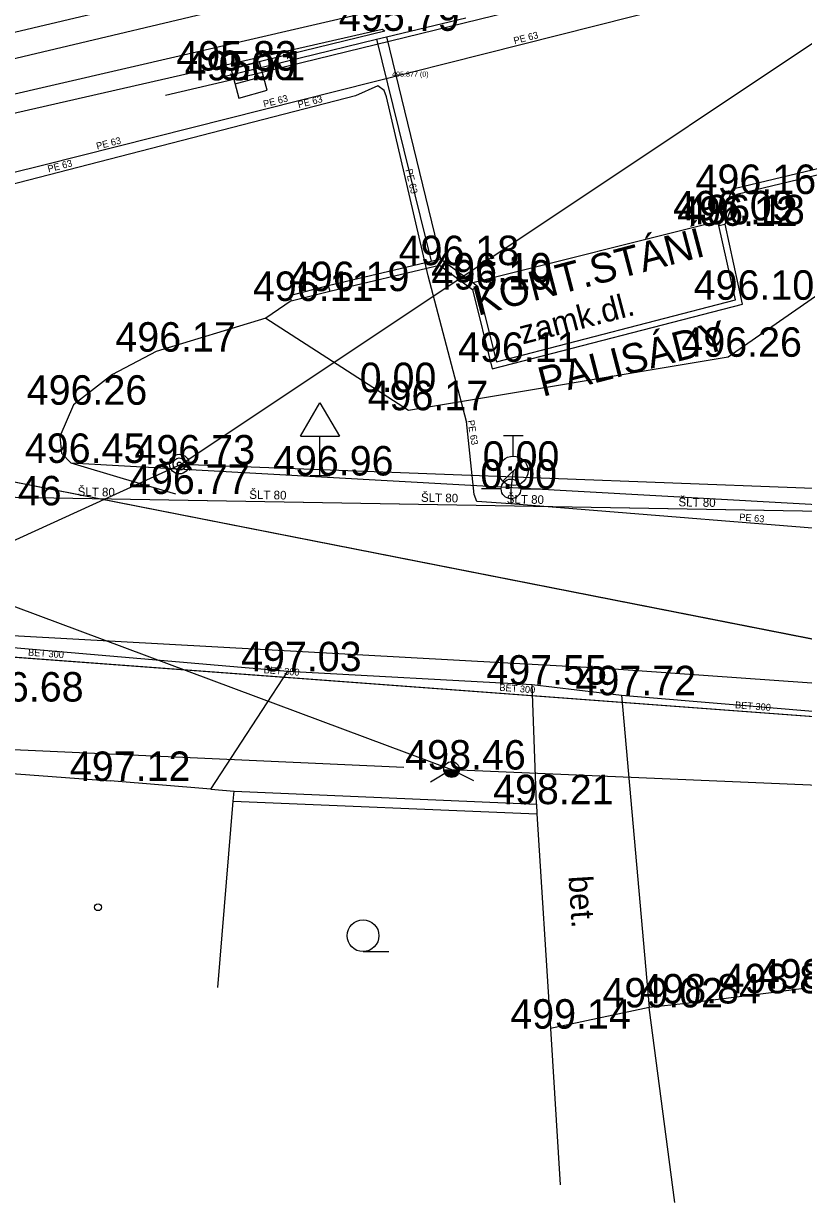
# Model space of a CAD drawing. Extents: x -669642 to -669119, y -1131006 to -1130466.
# Drawn here: x -669378.41 to -669358.57, y -1130646.29 to -1130616.3 of the extents above; entities that cross this region are included whole.
import ezdxf

# ---------------------------------------------------------------- set-up
doc = ezdxf.new("R2010")
doc.units = 0
for name, color, linetype in [('G_Bod_tecka', 7, 'Continuous'), ('G_Bod_vyska', 7, 'Continuous'), ('G_Breh_Teren', 7, 'Continuous'), ('G_Budovy-znacky', 7, 'Continuous'), ('G_Budovy_Objekty', 7, 'Continuous'), ('G_Budovy_vstupy', 7, 'Continuous'), ('G_Cesty_Schody', 7, 'Continuous'), ('G_Objekty_dopravni', 7, 'Continuous'), ('G_Plochy_zpevnene', 7, 'Continuous'), ('G_Ploty', 7, 'Continuous'), ('G_Ploty_vstupy', 7, 'Continuous'), ('G_Popisy_povrchu', 7, 'Continuous'), ('G_Poznamky_odkaz', 7, 'Continuous'), ('G_Site-kanalizace', 7, 'Continuous'), ('G_Site-Sloupy', 7, 'Continuous'), ('G_Site-vodovod', 7, 'Continuous'), ('G_Z_ELsilove_nadz_kotovane', 7, 'Continuous'), ('G_Z_ELsilove_podz_kotovane', 7, 'Continuous'), ('G_Z_KANAL_podz_kotovane', 7, 'Continuous'), ('G_Z_KANAL_podz_priblizne', 7, 'Continuous'), ('G_Z_PLYNY_podz_geodeticky', 7, 'Continuous'), ('G_Z_SPOJE_nadz_kotovane', 7, 'Continuous'), ('G_Z_VODA_podz_kotovane', 7, 'Continuous'), ('G_Zabradli_Svodidla', 7, 'Continuous'), ('G_Zelen-Znacky', 7, 'Continuous'), ('Vrstva 13', 7, 'Continuous'), ('Vrstva 17', 7, 'Continuous'), ('Vrstva 2', 7, 'Continuous'), ('Vrstva 21', 7, 'Continuous'), ('Vrstva 22', 7, 'Continuous'), ('Vrstva 25', 7, 'Continuous'), ('Vrstva 3', 7, 'Continuous'), ('Vrstva 4', 7, 'Continuous'), ('Vrstva 62', 7, 'Continuous'), ('Vrstva 8', 7, 'Continuous')]:
    doc.layers.add(name, color=color, linetype=linetype)

msp = doc.modelspace()

# ---------------------------------------------------------------- linework, layer by layer
at = {"layer": 'G_Bod_tecka'}
for p, q in [((-669369.22, -1130616.49), (-669369.22, -1130616.49)), ((-669373.36, -1130617.5), (-669373.36, -1130617.5)), ((-669373.21, -1130617.75), (-669373.21, -1130617.75)), ((-669372.67, -1130617.74), (-669372.67, -1130617.74)), ((-669360.26, -1130620.64), (-669360.26, -1130620.64)), ((-669360.74, -1130621.45), (-669360.74, -1130621.45)), ((-669360.68, -1130621.31), (-669360.68, -1130621.31)), ((-669360.56, -1130621.41), (-669360.56, -1130621.41)), ((-669367.83, -1130622.45), (-669367.83, -1130622.45)), ((-669366.99, -1130623.07), (-669366.99, -1130623.07)), ((-669366.98, -1130622.89), (-669366.98, -1130622.89)), ((-669371.6, -1130623.36), (-669371.6, -1130623.36)), ((-669370.62, -1130623.11), (-669370.62, -1130623.11)), ((-669360.3, -1130623.33), (-669360.3, -1130623.33)), ((-669375.04, -1130624.65), (-669375.04, -1130624.65)), ((-669360.48, -1130624.78), (-669360.48, -1130624.78)), ((-669366.38, -1130624.91), (-669366.38, -1130624.91)), ((-669369.08, -1130625.68), (-669369.08, -1130625.68)), ((-669377.14, -1130626), (-669377.14, -1130626)), ((-669368.62, -1130626.14), (-669368.62, -1130626.14)), ((-669377.21, -1130627.48), (-669377.21, -1130627.48)), ((-669374.41, -1130627.52), (-669374.41, -1130627.52)), ((-669370.87, -1130627.8), (-669370.87, -1130627.8)), ((-669365.95, -1130627.68), (-669365.95, -1130627.68)), ((-669366.01, -1130628.14), (-669366.01, -1130628.14)), ((-669374.55, -1130628.27), (-669374.55, -1130628.27)), ((-669371.69, -1130632.78), (-669371.69, -1130632.78)), ((-669365.47, -1130633.12), (-669365.47, -1130633.12)), ((-669363.2, -1130633.39), (-669363.2, -1130633.39)), ((-669367.52, -1130635.28), (-669367.52, -1130635.28)), ((-669376.21, -1130635.57), (-669376.21, -1130635.57)), ((-669365.36, -1130636.16), (-669365.36, -1130636.16)), ((-669359.46, -1130640.97), (-669359.46, -1130640.97)), ((-669362.49, -1130641.33), (-669362.49, -1130641.33)), ((-669361.55, -1130641.23), (-669361.55, -1130641.23)), ((-669365, -1130641.87), (-669365, -1130641.87))]:
    msp.add_line(p, q, dxfattribs=at)
at = {"layer": 'G_Breh_Teren'}
for p, q in [((-669348.63, -1130609.42), (-669399.78, -1130621.54)), ((-669348.48, -1130610.05), (-669399.67, -1130622.18)), ((-669373.65, -1130635.78), (-669371.69, -1130632.78))]:
    msp.add_line(p, q, dxfattribs=at)
for points in [[(-669372.25, -1130623.8), (-669368.62, -1130626.14), (-669360.48, -1130624.78), (-669351.48, -1130618.53)], [(-669377.21, -1130627.48), (-669354.27, -1130628.76), (-669343.54, -1130629.51), (-669334.11, -1130630.08), (-669322.15, -1130630.73)]]:
    msp.add_lwpolyline(points, dxfattribs=at)
at = {"layer": 'G_Budovy-znacky'}
msp.add_circle((-669376.519, -1130638.78), 0.0875, dxfattribs=at)
at = {"layer": 'G_Budovy_Objekty'}
for p, q in [((-669360.72, -1130621.44), (-669360.56, -1130621.41)), ((-669360.3, -1130623.33), (-669360.72, -1130621.44)), ((-669360.12, -1130623.44), (-669360.56, -1130621.41)), ((-669366.99, -1130623.07), (-669366.86, -1130622.98)), ((-669366.99, -1130623.07), (-669366.49, -1130625.09)), ((-669366.86, -1130622.98), (-669366.38, -1130624.91)), ((-669366.38, -1130624.91), (-669360.3, -1130623.33)), ((-669366.49, -1130625.09), (-669360.12, -1130623.44)), ((-669378.82, -1130635.37), (-669376.21, -1130635.57)), ((-669373.65, -1130635.78), (-669373.05, -1130635.83)), ((-669373.08, -1130636.08), (-669373.05, -1130635.83)), ((-669373.47, -1130640.82), (-669373.08, -1130636.08)), ((-669358.56, -1130640.85), (-669359.46, -1130640.97)), ((-669361.55, -1130641.23), (-669362.49, -1130641.33)), ((-669361.84, -1130646.29), (-669362.49, -1130641.33))]:
    msp.add_line(p, q, dxfattribs=at)
at = {"layer": 'G_Budovy_vstupy'}
for p, q in [((-669373.65, -1130635.78), (-669376.21, -1130635.57)), ((-669359.46, -1130640.97), (-669361.55, -1130641.23))]:
    msp.add_line(p, q, dxfattribs=at)
at = {"layer": 'G_Cesty_Schody'}
for p, q in [((-669369.43, -1130616.7), (-669369.18, -1130616.64)), ((-669369.18, -1130616.64), (-669367.8, -1130622.29)), ((-669360.68, -1130621.31), (-669360.37, -1130620.51)), ((-669366.98, -1130622.89), (-669360.68, -1130621.31)), ((-669360.72, -1130621.44), (-669360.68, -1130621.31)), ((-669368.04, -1130622.35), (-669367.8, -1130622.29)), ((-669367.8, -1130622.29), (-669366.98, -1130622.89)), ((-669370.66, -1130622.97), (-669370.62, -1130623.11)), ((-669366.98, -1130622.89), (-669366.86, -1130622.98))]:
    msp.add_line(p, q, dxfattribs=at)
msp.add_lwpolyline([(-669360.37, -1130620.51), (-669360.3, -1130620.49), (-669353.63, -1130618.9), (-669346.96, -1130617.3), (-669346.81, -1130617.27), (-669346.51, -1130617.27), (-669346.29, -1130617.31), (-669346.14, -1130617.36), (-669345.94, -1130617.49), (-669345.87, -1130617.57), (-669345.82, -1130617.66), (-669345.61, -1130618.16), (-669345.4, -1130618.65)], dxfattribs=at)
at = {"layer": 'G_Objekty_dopravni'}
for p, q in [((-669371.37, -1130626.8), (-669370.87, -1130625.95)), ((-669370.87, -1130625.95), (-669370.37, -1130626.8)), ((-669371.37, -1130626.8), (-669370.37, -1130626.8)), ((-669370.87, -1130627.8), (-669370.87, -1130626.8)), ((-669371.12, -1130627.8), (-669370.62, -1130627.8))]:
    msp.add_line(p, q, dxfattribs=at)
at = {"layer": 'G_Plochy_zpevnene'}
for p, q in [((-669401.89, -1130623.48), (-669355.52, -1130612.74)), ((-669369.18, -1130616.64), (-669367.16, -1130616.16)), ((-669373.36, -1130617.5), (-669369.22, -1130616.49)), ((-669373.32, -1130617.65), (-669369.43, -1130616.7)), ((-669369.43, -1130616.7), (-669368.04, -1130622.35)), ((-669373.32, -1130617.65), (-669373.36, -1130617.5)), ((-669360.56, -1130621.41), (-669360.26, -1130620.64)), ((-669370.66, -1130622.97), (-669368.04, -1130622.35)), ((-669370.62, -1130623.11), (-669367.83, -1130622.45)), ((-669367.83, -1130622.45), (-669366.99, -1130623.07)), ((-669371.64, -1130623.22), (-669370.66, -1130622.97)), ((-669371.6, -1130623.36), (-669372.25, -1130623.8)), ((-669371.64, -1130623.22), (-669371.6, -1130623.36)), ((-669371.6, -1130623.36), (-669370.62, -1130623.11)), ((-669365.47, -1130633.12), (-669363.2, -1130633.39)), ((-669365.36, -1130636.16), (-669365.47, -1130633.12)), ((-669363.2, -1130633.39), (-669362.49, -1130641.33))]:
    msp.add_line(p, q, dxfattribs=at)
for points in [[(-669403.47, -1130624.24), (-669369.29, -1130616.45), (-669369.22, -1130616.49)], [(-669360.26, -1130620.64), (-669353.56, -1130619.03), (-669351.48, -1130618.53)], [(-669372.25, -1130623.8), (-669375.04, -1130624.65), (-669376.15, -1130625.23), (-669377.14, -1130626), (-669377.49, -1130626.81), (-669377.45, -1130627.23), (-669377.21, -1130627.48), (-669375.88, -1130627.88), (-669374.55, -1130628.27)], [(-669381.36, -1130631.9), (-669380.46, -1130632.02), (-669371.69, -1130632.78), (-669365.47, -1130633.12)], [(-669363.2, -1130633.39), (-669342.9, -1130635.08), (-669335.46, -1130635.11)]]:
    msp.add_lwpolyline(points, dxfattribs=at)
at = {"layer": 'G_Ploty'}
for p, q in [((-669373.05, -1130635.83), (-669365.36, -1130636.16)), ((-669373.08, -1130636.08), (-669365.35, -1130636.41)), ((-669365.36, -1130636.16), (-669365.35, -1130636.41)), ((-669365.35, -1130636.41), (-669365, -1130641.87)), ((-669365, -1130641.87), (-669364.76, -1130645.84))]:
    msp.add_line(p, q, dxfattribs=at)
at = {"layer": 'G_Ploty_vstupy'}
msp.add_line((-669362.49, -1130641.33), (-669365, -1130641.87), dxfattribs=at)
at = {"layer": 'G_Site-kanalizace'}
msp.add_lwpolyline([(-669372.933, -1130618.2), (-669372.21, -1130618.002), (-669372.408, -1130617.278), (-669373.131, -1130617.476)], close=True, dxfattribs=at)
msp.add_lwpolyline([(-669373.032, -1130617.839), (-669372.308, -1130617.641)], dxfattribs=at)
at = {"layer": 'G_Site-Sloupy'}
for centre, radius in [((-669374.45, -1130627.51), 0.25), ((-669374.45, -1130627.51), 0.158), ((-669374.45, -1130627.51), 0.05), ((-669367.52, -1130635.28), 0.2)]:
    msp.add_circle(centre, radius, dxfattribs=at)
for radius in [0.18, 0.16, 0.14, 0.12, 0.1, 0.08, 0.06, 0.04, 0.02]:
    msp.add_arc((-669367.52, -1130635.28), radius, 180, 0, dxfattribs=at)
at = {"layer": 'G_Site-vodovod'}
for p, q in [((-669366.2, -1130626.78), (-669365.7, -1130626.78)), ((-669365.95, -1130627.305), (-669365.95, -1130626.78)), ((-669366.215, -1130627.945), (-669365.685, -1130627.415)), ((-669366.26, -1130628.14), (-669366.76, -1130628.14)), ((-669365.76, -1130628.14), (-669365.26, -1130628.14))]:
    msp.add_line(p, q, dxfattribs=at)
for centre, radius in [((-669365.95, -1130627.68), 0.375), ((-669366.01, -1130628.14), 0.25)]:
    msp.add_circle(centre, radius, dxfattribs=at)
at = {"layer": 'G_Z_ELsilove_nadz_kotovane'}
for points in [[(-669396.407, -1130624.513), (-669367.525, -1130635.278)], [(-669367.525, -1130635.278), (-669368.057, -1130635.602)], [(-669367.525, -1130635.278), (-669335.337, -1130636.655)], [(-669367.525, -1130635.278), (-669366.967, -1130635.56)]]:
    msp.add_lwpolyline(points, dxfattribs=at)
at = {"layer": 'G_Z_ELsilove_podz_kotovane'}
for points in [[(-669190.087, -1130609.65), (-669214.93, -1130618.33), (-669245.84, -1130627.72), (-669272.45, -1130632.83), (-669315.37, -1130634.54), (-669335.4, -1130636.48), (-669397.44, -1130624.27)], [(-669368.738, -1130635.227), (-669382.808, -1130634.59), (-669383.259, -1130634.946)]]:
    msp.add_lwpolyline(points, dxfattribs=at)
at = {"layer": 'G_Z_KANAL_podz_kotovane'}
for points in [[(-669297.24, -1130603.09), (-669298.05, -1130602.99), (-669299.58, -1130603.49), (-669318.15, -1130605.49), (-669338.13, -1130610.04), (-669358.26, -1130614.95), (-669377.9, -1130619.91), (-669396.08, -1130624.4), (-669396.67, -1130624.98), (-669397.62, -1130625.22), (-669398.32, -1130624.92), (-669403.62, -1130625.69)], [(-669312.15, -1130634.23), (-669337.66, -1130635.9), (-669338.26, -1130635.96), (-669338.66, -1130636.11), (-669339.1, -1130636.19), (-669339.37, -1130636.12), (-669347.02, -1130636.1), (-669347.25, -1130635.99), (-669347.18, -1130634.79), (-669346.34, -1130630.41), (-669346.31, -1130630.26), (-669347.15, -1130630.24), (-669347.21, -1130630.14), (-669356.13, -1130629.32), (-669366.01, -1130628.52), (-669366.88, -1130628.46), (-669366.95, -1130628.28), (-669367.14, -1130626.43), (-669368.12, -1130622.72), (-669369.18, -1130618.17), (-669369.24, -1130618.01), (-669369.4, -1130617.89), (-669369.97, -1130618.14), (-669381.44, -1130621.1)], [(-669365.95, -1130627.68), (-669366.01, -1130628.14), (-669366.01, -1130628.52)]]:
    msp.add_lwpolyline(points, dxfattribs=at)
at = {"layer": 'G_Z_KANAL_podz_priblizne'}
msp.add_lwpolyline([(-669339.24, -1130635.36), (-669347.68, -1130634.73), (-669399.21, -1130630.9)], dxfattribs=at)
at = {"layer": 'G_Z_PLYNY_podz_geodeticky'}
msp.add_lwpolyline([(-669392.65, -1130633.93), (-669386.63, -1130631.49), (-669386.35, -1130631.52), (-669380.25, -1130631.8), (-669378.54, -1130631.88), (-669363.63, -1130632.7), (-669336.16, -1130634.64), (-669320.1, -1130633.99), (-669318.23, -1130633.85), (-669314.82, -1130633.7), (-669300.73, -1130631.99), (-669294.87, -1130631.62), (-669289.57, -1130631.26), (-669280.66, -1130630.72), (-669273, -1130630.23), (-669260.29, -1130628.84), (-669256.85, -1130628.17), (-669248.71, -1130626.58), (-669247.25, -1130626.36), (-669236.34, -1130624.26), (-669226.66, -1130620.52), (-669226.32, -1130620.39), (-669199.17, -1130609.49)], dxfattribs=at)
at = {"layer": 'G_Z_SPOJE_nadz_kotovane'}
for points in [[(-669374.41, -1130627.52), (-669335.65, -1130601.68), (-669301.39, -1130595.67), (-669297.16, -1130573.48)], [(-669374.41, -1130627.52), (-669403.46, -1130640.77)], [(-669343.11, -1130628.71), (-669374.41, -1130627.52), (-669403.46, -1130640.77)]]:
    msp.add_lwpolyline(points, dxfattribs=at)
at = {"layer": 'G_Z_VODA_podz_kotovane'}
msp.add_lwpolyline([(-669190.087, -1130598.609), (-669191.78, -1130598.9), (-669199.31, -1130600.19), (-669200.73, -1130600.43), (-669203.35, -1130600.88), (-669220.34, -1130612.26), (-669232.7, -1130618.9), (-669254.98, -1130624.08), (-669275.83, -1130626.1), (-669278.94, -1130626.4), (-669285, -1130627.12), (-669289.19, -1130627.61), (-669294.13, -1130627.47), (-669320.23, -1130629.57), (-669324.19, -1130629.31), (-669335.63, -1130629.11), (-669379.12, -1130628.35)], dxfattribs=at)
at = {"layer": 'G_Zabradli_Svodidla'}
for p, q in [((-669373.21, -1130617.75), (-669359.78, -1130614.47)), ((-669374.8, -1130618.13), (-669373.21, -1130617.75))]:
    msp.add_line(p, q, dxfattribs=at)
at = {"layer": 'G_Zelen-Znacky'}
msp.add_line((-669369.772, -1130639.91), (-669369.122, -1130639.907), dxfattribs=at)
msp.add_circle((-669369.773, -1130639.507), 0.403, dxfattribs=at)
at = {"layer": 'Vrstva 13'}
msp.add_lwpolyline([(-669365.95, -1130627.68), (-669366.01, -1130628.14), (-669366.01, -1130628.52)], dxfattribs=at)
at = {"layer": 'Vrstva 17'}
msp.add_lwpolyline([(-669339.24, -1130635.36), (-669347.68, -1130634.73), (-669399.213, -1130630.895)], dxfattribs=at)
at = {"layer": 'Vrstva 21'}
msp.add_lwpolyline([(-669297.24, -1130603.09), (-669298.05, -1130602.99), (-669299.58, -1130603.49), (-669318.15, -1130605.49), (-669338.13, -1130610.04), (-669358.26, -1130614.95), (-669377.9, -1130619.91), (-669396.08, -1130624.4), (-669396.67, -1130624.98), (-669397.62, -1130625.22), (-669398.32, -1130624.92), (-669403.622, -1130625.686)], dxfattribs=at)
at = {"layer": 'Vrstva 22'}
msp.add_lwpolyline([(-669312.15, -1130634.23), (-669337.66, -1130635.9), (-669338.26, -1130635.96), (-669338.66, -1130636.11), (-669339.1, -1130636.19), (-669339.37, -1130636.12), (-669347.02, -1130636.1), (-669347.25, -1130635.99), (-669347.18, -1130634.79), (-669346.34, -1130630.41), (-669346.314, -1130630.262), (-669347.15, -1130630.24), (-669347.21, -1130630.14), (-669356.13, -1130629.32), (-669366.01, -1130628.52), (-669366.88, -1130628.46), (-669366.95, -1130628.28), (-669367.14, -1130626.43), (-669368.12, -1130622.72), (-669369.18, -1130618.17), (-669369.24, -1130618.01), (-669369.4, -1130617.89), (-669369.97, -1130618.14), (-669381.44, -1130621.1)], dxfattribs=at)
at = {"layer": 'Vrstva 25'}
msp.add_lwpolyline([(-669190.087, -1130598.606), (-669191.784, -1130598.897), (-669199.313, -1130600.19), (-669200.733, -1130600.434), (-669203.348, -1130600.883), (-669220.34, -1130612.258), (-669232.701, -1130618.903), (-669254.976, -1130624.076), (-669275.828, -1130626.101), (-669278.938, -1130626.403), (-669284.999, -1130627.117), (-669289.19, -1130627.61), (-669294.131, -1130627.469), (-669320.233, -1130629.567), (-669324.191, -1130629.306), (-669335.635, -1130629.107), (-669379.115, -1130628.353)], dxfattribs=at)
at = {"layer": 'Vrstva 62'}
msp.add_line((-669335.4, -1130636.48), (-669397.44, -1130624.27), dxfattribs=at)
at = {"layer": 'Vrstva 8'}
msp.add_line((-669369.24, -1130618.01), (-669369.24, -1130618.01), dxfattribs=at)

# ---------------------------------------------------------------- texts
at = {"layer": 'G_Bod_vyska'}
for s, p in [('495.79', (-669370.388, -1130616.49)), ('495.83', (-669374.526, -1130617.5)), ('495.71', (-669374.314, -1130617.75)), ('0.00', (-669373.45, -1130617.74)), ('496.16', (-669361.312, -1130620.64)), ('496.09', (-669361.883, -1130621.31)), ('496.12', (-669361.778, -1130621.45)), ('496.18', (-669361.598, -1130621.41)), ('496.18', (-669368.868, -1130622.45)), ('496.10', (-669368.04, -1130622.89)), ('496.19', (-669371.66, -1130623.11)), ('496.19', (-669368.03, -1130623.07)), ('496.11', (-669372.576, -1130623.36)), ('496.10', (-669361.36, -1130623.33)), ('496.17', (-669376.078, -1130624.65)), ('496.11', (-669367.356, -1130624.91)), ('496.26', (-669361.673, -1130624.78)), ('0.00', (-669369.86, -1130625.68)), ('496.26', (-669378.333, -1130626)), ('496.17', (-669369.658, -1130626.14)), ('496.45', (-669378.38, -1130627.48)), ('496.73', (-669375.59, -1130627.52)), ('0.00', (-669366.73, -1130627.68)), ('496.96', (-669372.065, -1130627.8)), ('496.77', (-669375.73, -1130628.27)), ('0.00', (-669366.79, -1130628.14)), ('496.46', (-669380.513, -1130628.56)), ('497.03', (-669372.878, -1130632.78)), ('497.55', (-669366.636, -1130633.12)), ('497.72', (-669364.366, -1130633.39)), ('496.68', (-669379.953, -1130633.55)), ('498.46', (-669368.7, -1130635.28)), ('497.12', (-669377.234, -1130635.57)), ('498.21', (-669366.464, -1130636.16)), ('498.78', (-669359.726, -1130640.85)), ('498.84', (-669362.716, -1130641.23)), ('498.84', (-669360.626, -1130640.97)), ('499.02', (-669363.68, -1130641.33)), ('499.14', (-669366.026, -1130641.87))]:
    msp.add_text(s, height=0.75, dxfattribs=at).set_placement(p)
at = {"layer": 'G_Popisy_povrchu'}
for s, rotation, p in [('zamk.dl.', 14.7344, (-669365.713, -1130624.469)), ('bet.', 273.576, (-669364.545, -1130637.993))]:
    msp.add_text(s, height=0.6, rotation=rotation, dxfattribs=at).set_placement(p)
at = {"layer": 'G_Poznamky_odkaz'}
for s, rotation, p in [('KONT.STÁNÍ', 14.7344, (-669366.854, -1130623.741)), ('PALISÁDY', 14.5644, (-669365.203, -1130625.801))]:
    msp.add_text(s, height=0.75, rotation=rotation, dxfattribs=at).set_placement(p)
at = {"layer": 'Vrstva 2'}
msp.add_text('495.877 (0)', height=0.13163, dxfattribs=at).set_placement((-669369.035, -1130617.657))
at = {"layer": 'Vrstva 3'}
for s, rotation, p in [('PE 63', 14.1942, (-669365.918, -1130616.83)), ('PE 63', 14.1696, (-669372.291, -1130618.439)), ('PE 63', 14.3882, (-669371.41, -1130618.456)), ('PE 63', 14.1696, (-669376.539, -1130619.512)), ('PE 63', 14.3758, (-669377.776, -1130620.091)), ('PE 63', 283.0602, (-669368.694, -1130620.024)), ('PE 63', 279.4993, (-669367.118, -1130626.405)), ('PE 63', 355.3942, (-669360.206, -1130628.941)), ('BET 300', 355.7441, (-669378.304, -1130632.381)), ('BET 300', 355.7441, (-669372.307, -1130632.827)), ('BET 300', 355.7466, (-669366.31, -1130633.274)), ('BET 300', 355.7441, (-669360.313, -1130633.72))]:
    msp.add_text(s, height=0.1755, rotation=rotation, dxfattribs=at).set_placement(p)
at = {"layer": 'Vrstva 4'}
for rotation, p in [(359.0157, (-669377.039, -1130628.319)), (359.0157, (-669372.671, -1130628.395)), (359.0316, (-669368.302, -1130628.47)), (359.0157, (-669366.118, -1130628.508)), (359.0157, (-669361.749, -1130628.584))]:
    msp.add_text('ŠLT 80', height=0.2194, rotation=rotation, dxfattribs=at).set_placement(p)

doc.saveas('drawing.dxf')
